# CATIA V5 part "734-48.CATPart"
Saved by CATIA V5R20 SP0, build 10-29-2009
Part number: 734-48
Bounding box of the stored display mesh (mm): x -40 to 40, y -40 to 40, z -60 to 71
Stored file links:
  C:\Users\Utente\Desktop\IO LAVORO\3D X SITO CF\X SITO\734\734-48.CATPart
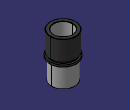
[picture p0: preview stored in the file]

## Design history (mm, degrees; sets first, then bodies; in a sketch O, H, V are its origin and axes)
Set1
  DatumSurface1 to DatumSurface25 "734-48"
Body1 (main body)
